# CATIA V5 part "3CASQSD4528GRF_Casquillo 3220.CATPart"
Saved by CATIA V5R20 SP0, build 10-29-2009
Part number: 3CASQSD4528GRF_Casquillo 3220
Revision: ANY
Definition: UNKNOWN
Nomenclature: 3CASQSD4528GRF_Casquillo 3220
Source: Unknown
Bounding box of the stored display mesh (mm): x -13.8 to 31.2, y -10.25 to 10.25, z -10.25 to 10.25
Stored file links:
  C:\Users\Utente\Desktop\IO LAVORO\3D X SITO CF\CUMSA\3D files SD\SD 4528\3CASQSD4528GRF_Casquillo 3220.CATPart
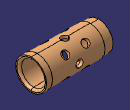
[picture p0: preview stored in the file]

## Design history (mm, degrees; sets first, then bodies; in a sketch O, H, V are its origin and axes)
Body1 "MatrizC1" (main body)
  Solid1: solid without history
